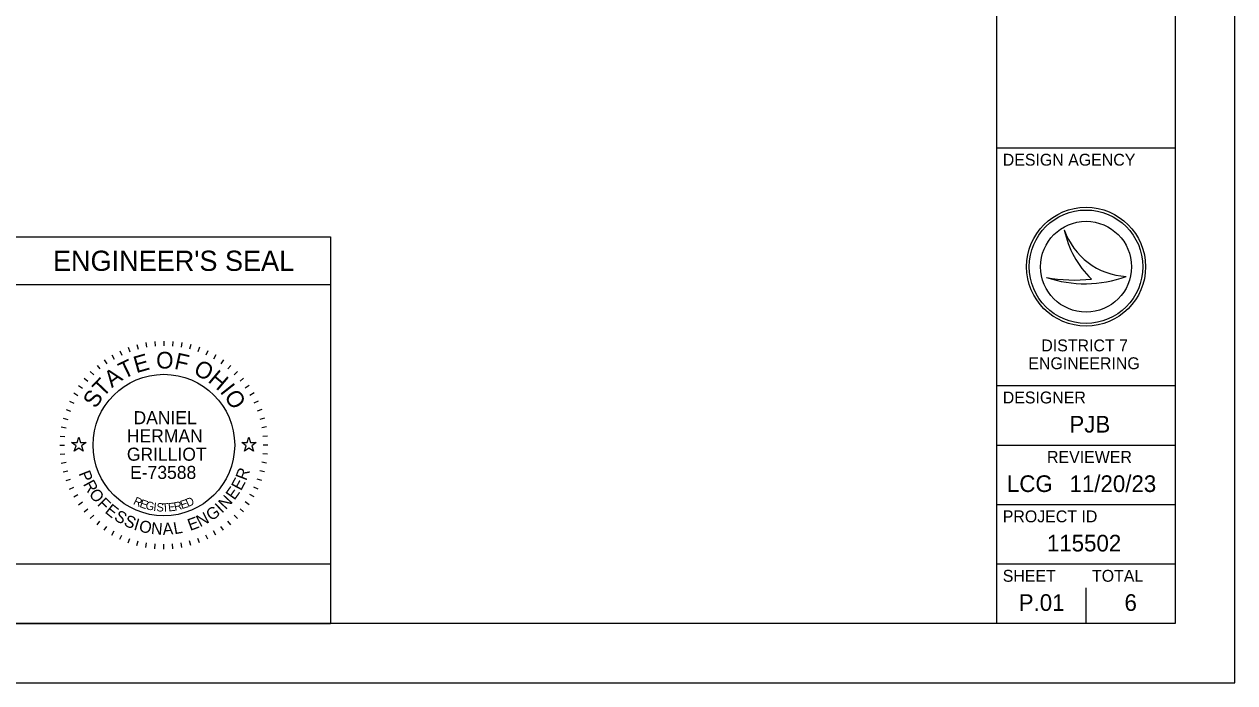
# Model space of a CAD drawing. Extents: x 0 to 34, y 0 to 22.
# Drawn here: x 23.83 to 34, y 0 to 5.54 of the extents above; entities that cross this region are included whole.
import ezdxf

# ---------------------------------------------------------------- set-up
doc = ezdxf.new("R2010")
doc.units = 0
for name, color, linetype in [('Default', 7, 'Continuous'), ('SH_Border', 7, 'Continuous'), ('SH_Cut_Line', 7, 'Continuous'), ('SH_Data', 7, 'Continuous'), ('SH_Text', 7, 'Continuous')]:
    doc.layers.add(name, color=color, linetype=linetype)

msp = doc.modelspace()

# ---------------------------------------------------------------- linework, layer by layer
at = {"layer": 'Default'}
for points in [[(24.224, 2.02), (24.271, 2.02), (24.285, 2.065), (24.299, 2.02), (24.346, 2.02), (24.308, 1.992), (24.323, 1.948), (24.285, 1.975), (24.247, 1.948), (24.262, 1.992)], [(25.654, 2.02), (25.701, 2.02), (25.715, 2.065), (25.729, 2.02), (25.776, 2.02), (25.738, 1.992), (25.753, 1.948), (25.715, 1.975), (25.677, 1.948), (25.692, 1.992)]]:
    msp.add_lwpolyline(points, close=True, dxfattribs=at)
at = {"layer": 'SH_Border'}
for p, q in [((32, 0.5), (32, 21.5)), ((32, 4.5), (33.5, 4.5)), ((32, 2.5), (33.5, 2.5)), ((32, 2), (33.5, 2)), ((32, 1.5), (33.5, 1.5)), ((32, 1), (33.5, 1))]:
    msp.add_line(p, q, dxfattribs=at)
msp.add_lwpolyline([(1.5, 21.5), (33.5, 21.5), (33.5, 0.5), (1.5, 0.5)], close=True, dxfattribs=at)
at = {"layer": 'SH_Cut_Line'}
msp.add_lwpolyline([(0, 0), (34, 0), (34, 22), (0, 22)], close=True, dxfattribs=at)
at = {"layer": 'SH_Data'}
for p, q in [((32.567, 3.81), (32.567, 3.81)), ((23.6, 3.75), (26.4, 3.75)), ((26.4, 3.75), (26.4, 0.5)), ((32.75, 3.5), (32.75, 3.5)), ((32.417, 3.41), (32.417, 3.41)), ((33.087, 3.419), (33.087, 3.419)), ((23.6, 3.35), (26.4, 3.35)), ((24.848, 2.862), (24.855, 2.822)), ((24.924, 2.872), (24.927, 2.832)), ((25, 2.875), (25, 2.835)), ((25.076, 2.872), (25.073, 2.832)), ((25.152, 2.862), (25.145, 2.822)), ((24.563, 2.758), (24.583, 2.723)), ((24.63, 2.793), (24.647, 2.757)), ((24.701, 2.822), (24.714, 2.785)), ((24.774, 2.845), (24.784, 2.807)), ((25.226, 2.845), (25.216, 2.807)), ((25.299, 2.822), (25.286, 2.785)), ((25.37, 2.793), (25.353, 2.757)), ((25.437, 2.758), (25.417, 2.723)), ((24.438, 2.67), (24.463, 2.64)), ((24.498, 2.717), (24.521, 2.684)), ((25.502, 2.717), (25.479, 2.684)), ((25.562, 2.67), (25.537, 2.64)), ((24.33, 2.562), (24.36, 2.537)), ((24.381, 2.619), (24.41, 2.59)), ((25.619, 2.619), (25.59, 2.59)), ((25.67, 2.562), (25.64, 2.537)), ((24.283, 2.502), (24.316, 2.479)), ((25.717, 2.502), (25.684, 2.479)), ((24.207, 2.37), (24.243, 2.353)), ((24.242, 2.438), (24.277, 2.418)), ((25.758, 2.438), (25.723, 2.418)), ((25.793, 2.37), (25.757, 2.353)), ((24.178, 2.299), (24.215, 2.286)), ((25.822, 2.299), (25.785, 2.286)), ((24.138, 2.152), (24.178, 2.145)), ((24.155, 2.226), (24.193, 2.216)), ((25.845, 2.226), (25.807, 2.216)), ((25.862, 2.152), (25.822, 2.145)), ((24.128, 2.076), (24.168, 2.073)), ((25.872, 2.076), (25.832, 2.073)), ((24.125, 2), (24.165, 2)), ((25.875, 2), (25.835, 2)), ((24.128, 1.924), (24.168, 1.927)), ((24.138, 1.848), (24.178, 1.855)), ((25.862, 1.848), (25.822, 1.855)), ((25.872, 1.924), (25.832, 1.927)), ((24.155, 1.774), (24.193, 1.784)), ((25.845, 1.774), (25.807, 1.784)), ((24.178, 1.701), (24.215, 1.714)), ((24.207, 1.63), (24.243, 1.647)), ((25.793, 1.63), (25.757, 1.647)), ((25.822, 1.701), (25.785, 1.714)), ((24.242, 1.563), (24.277, 1.583)), ((25.758, 1.563), (25.723, 1.583)), ((24.283, 1.498), (24.316, 1.521)), ((24.33, 1.438), (24.36, 1.463)), ((25.67, 1.438), (25.64, 1.463)), ((25.717, 1.498), (25.684, 1.521)), ((24.381, 1.381), (24.41, 1.41)), ((24.438, 1.33), (24.463, 1.36)), ((25.562, 1.33), (25.537, 1.36)), ((25.619, 1.381), (25.59, 1.41)), ((24.498, 1.283), (24.521, 1.316)), ((24.563, 1.242), (24.583, 1.277)), ((24.63, 1.207), (24.647, 1.243)), ((25.37, 1.207), (25.353, 1.243)), ((25.437, 1.242), (25.417, 1.277)), ((25.502, 1.283), (25.479, 1.316)), ((24.701, 1.178), (24.714, 1.215)), ((24.774, 1.155), (24.784, 1.193)), ((24.848, 1.138), (24.855, 1.178)), ((24.924, 1.128), (24.927, 1.168)), ((25, 1.125), (25, 1.165)), ((25.076, 1.128), (25.073, 1.168)), ((25.152, 1.138), (25.145, 1.178)), ((25.226, 1.155), (25.216, 1.193)), ((25.299, 1.178), (25.286, 1.215)), ((32.75, 0.5), (32.75, 0.8)), ((32.375, 0.675), (32.375, 0.675)), ((23.6, 0.5), (26.4, 0.5))]:
    msp.add_line(p, q, dxfattribs=at)
msp.add_lwpolyline([(23.6, 0.5), (23.6, 1), (26.4, 1), (26.4, 0.5)], close=True, dxfattribs=at)
for centre, radius in [((32.75, 3.5), 0.5), ((32.75, 3.5), 0.477), ((32.75, 3.5), 0.477), ((32.75, 3.5), 0.382), ((25, 2), 0.595)]:
    msp.add_circle(centre, radius, dxfattribs=at)
for centre, radius, start, end in [((33.116, 3.998), 0.58, 198.9257, 198.9319), ((33.347, 3.97), 0.796, 191.6379, 191.6421), ((33.116, 3.998), 0.58, 198.9319, 267.1657), ((33.347, 3.97), 0.796, 191.6421, 226.0947), ((32.739, 4.37), 1.013, 251.4576, 290.0832), ((32.648, 4.654), 1.266, 259.4964, 259.4995), ((32.739, 4.37), 1.013, 251.4527, 251.4576), ((32.648, 4.654), 1.266, 259.4995, 276.6672)]:
    msp.add_arc(centre, radius, start, end, dxfattribs=at)

# ---------------------------------------------------------------- texts
for s, height, p in [('DESIGN AGENCY', 0.1, (32.05, 4.35)), ("ENGINEER'S SEAL", 0.17, (24.068, 3.465)), ('DESIGNER', 0.1, (32.05, 2.35)), ('DANIEL', 0.11, (24.745, 2.175)), ('PJB', 0.14, (32.61, 2.105)), ('HERMAN', 0.11, (24.689, 2.022)), ('GRILLIOT', 0.11, (24.689, 1.868)), ('REVIEWER', 0.1, (32.422, 1.85)), ('E-73588', 0.11, (24.716, 1.715)), ('LCG', 0.14, (32.085, 1.605)), ('11/20/23', 0.14, (32.611, 1.605)), ('PROJECT ID', 0.1, (32.05, 1.35)), ('115502', 0.14, (32.421, 1.105)), ('SHEET', 0.1, (32.05, 0.85)), ('TOTAL', 0.1, (32.8, 0.85)), ('P.01', 0.14, (32.184, 0.605)), ('6', 0.14, (33.073, 0.605))]:
    msp.add_text(s, height=height, dxfattribs=at).set_placement(p)
for s, height, rotation, p in [('E', 0.14, 15.7571, (24.768, 2.604)), ('O', 0.14, 359.7812, (24.935, 2.644)), ('F', 0.14, 347.4362, (25.081, 2.642)), ('T', 0.14, 25.7167, (24.662, 2.552)), ('O', 0.14, 332.2586, (25.24, 2.602)), ('T', 0.14, 46.4344, (24.488, 2.396)), ('A', 0.14, 36.4747, (24.563, 2.478)), ('H', 0.14, 319.9136, (25.363, 2.536)), ('S', 0.14, 57.1924, (24.428, 2.301)), ('I', 0.14, 308.367, (25.466, 2.448)), ('O', 0.14, 303.1491, (25.502, 2.409)), ('P', 0.1, 291.494, (24.282, 1.762)), ('R', 0.1, 69.2322, (25.692, 1.695)), ('R', 0.1, 298.7311, (24.319, 1.672)), ('E', 0.1, 54.758, (25.593, 1.531)), ('E', 0.1, 61.9951, (25.648, 1.61)), ('O', 0.1, 306.4666, (24.365, 1.588)), ('F', 0.1, 314.7068, (24.434, 1.498)), ('R', 0.07, 334.487, (24.737, 1.505)), ('E', 0.07, 341.04, (24.791, 1.48)), ('G', 0.07, 347.4752, (24.841, 1.462)), ('E', 0.07, 17.6836, (25.15, 1.46)), ('D', 0.07, 23.3052, (25.201, 1.477)), ('N', 0.1, 47.0224, (25.52, 1.451)), ('E', 0.1, 321.4393, (24.498, 1.435)), ('S', 0.1, 328.6764, (24.574, 1.375)), ('I', 0.07, 353.7858, (24.909, 1.447)), ('S', 0.07, 356.8926, (24.936, 1.443)), ('T', 0.07, 3.0061, (24.986, 1.439)), ('E', 0.07, 6.0117, (25.039, 1.441)), ('R', 0.07, 11.9184, (25.092, 1.447)), ('N', 0.1, 27.3113, (25.304, 1.308)), ('G', 0.1, 35.0469, (25.398, 1.357)), ('I', 0.1, 43.287, (25.487, 1.421)), ('S', 0.1, 335.9134, (24.656, 1.327)), ('I', 0.1, 343.1505, (24.741, 1.29)), ('O', 0.1, 346.8859, (24.784, 1.275)), ('N', 0.1, 355.1261, (24.889, 1.252)), ('A', 0.1, 2.8617, (24.992, 1.244)), ('L', 0.1, 10.0987, (25.089, 1.249)), ('E', 0.1, 20.0742, (25.221, 1.277))]:
    msp.add_text(s, height=height, rotation=rotation, dxfattribs=at).set_placement(p)
at = {"layer": 'SH_Text'}
for s, p in [('DISTRICT 7', (32.374, 2.788)), ('ENGINEERING', (32.265, 2.638))]:
    msp.add_text(s, height=0.1, dxfattribs=at).set_placement(p)

doc.saveas('drawing.dxf')
